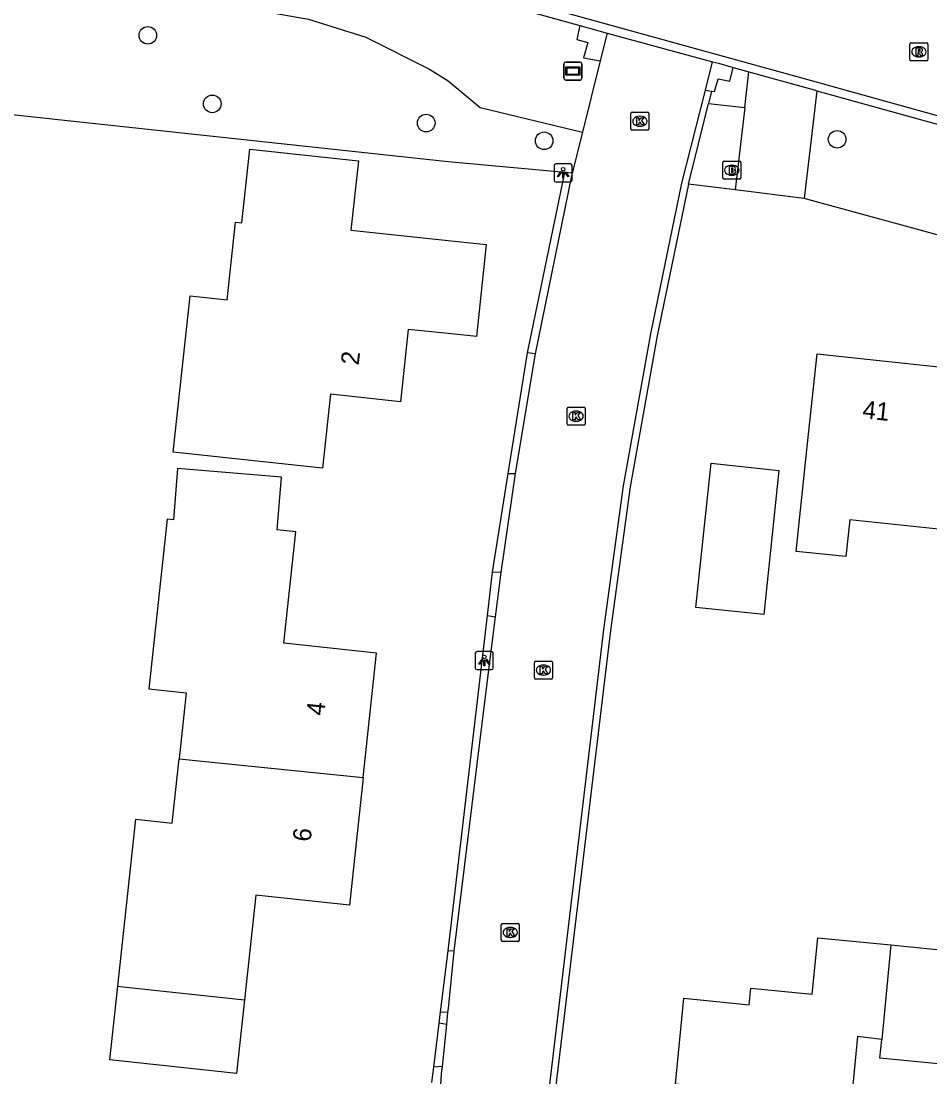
# Model space of a CAD drawing. Extents: x 162157 to 163165, y 378998 to 380775.
# Drawn here: x 162476.3 to 162526.7, y 380574.4 to 380633 of the extents above; entities that cross this region are included whole.
import ezdxf

# ---------------------------------------------------------------- set-up
doc = ezdxf.new("R2010")
doc.units = 0
for name, color, linetype in [('IMGEO_Boom', 7, 'Continuous'), ('IMGEO_Brandkraan', 7, 'Continuous'), ('IMGEO_Groenvoorziening', 7, 'Continuous'), ('IMGEO_Kolk', 7, 'Continuous'), ('IMGEO_Lichtpunt', 7, 'Continuous'), ('IMGEO_Pand', 7, 'Continuous'), ('IMGEO_Pand_nummerreeks', 7, 'Continuous'), ('IMGEO_Rijbaan_lokaal_gesloten', 7, 'Continuous'), ('IMGEO_Rijbaan_lokaal_open', 7, 'Continuous'), ('IMGEO_Rioolput', 7, 'Continuous'), ('IMGEO_Straatnaambord', 7, 'Continuous'), ('IMGEO_Voetpad_open', 7, 'Continuous')]:
    doc.layers.add(name, color=color, linetype=linetype)

msp = doc.modelspace()

# ---------------------------------------------------------------- linework, layer by layer
at = {"layer": 'IMGEO_Boom'}
for centre in [(162483.344, 380632.211), (162486.919, 380628.409), (162498.79, 380627.343), (162505.335, 380626.359), (162521.591, 380626.441)]:
    msp.add_circle(centre, 0.489, dxfattribs=at)
at = {"layer": 'IMGEO_Brandkraan'}
for p, q in [((162515.25, 380624.301), (162515.25, 380625.153)), ((162515.325, 380625.227), (162516.177, 380625.227)), ((162516.251, 380625.153), (162516.251, 380624.301)), ((162515.761, 380624.447), (162515.736, 380624.447)), ((162515.738, 380625.007), (162515.763, 380625.007)), ((162516.177, 380624.227), (162515.325, 380624.227))]:
    msp.add_line(p, q, dxfattribs=at)
for points in [[(162515.25, 380624.301), (162515.25, 380625.153)], [(162515.325, 380625.227), (162516.177, 380625.227)], [(162516.251, 380625.153), (162516.251, 380624.301)], [(162515.598, 380624.927), (162515.598, 380624.527), (162515.811, 380624.527)], [(162515.829, 380624.927), (162515.598, 380624.927)], [(162515.777, 380624.846), (162515.723, 380624.846), (162515.723, 380624.77)], [(162515.723, 380624.77), (162515.776, 380624.77)], [(162515.785, 380624.694), (162515.723, 380624.694), (162515.723, 380624.613)], [(162515.723, 380624.613), (162515.785, 380624.613)], [(162516.177, 380624.227), (162515.325, 380624.227)]]:
    msp.add_lwpolyline(points, dxfattribs=at)
for centre, radius, start, end in [((162515.327, 380625.151), 0.0765, 91.55205, 178.44795), ((162515.327, 380625.151), 0.0765, 91.55205, 178.44795), ((162516.175, 380625.151), 0.0765, 1.55205, 88.44795), ((162516.175, 380625.151), 0.0765, 1.55205, 88.44795), ((162515.778, 380624.808), 0.0379, 267.82845, 90.93552), ((162515.786, 380624.653), 0.0404, 269.87594, 90.50774), ((162515.817, 380624.778), 0.251, 268.66757, 293.53466), ((162515.833, 380624.782), 0.145, 59.4692, 91.53667), ((162515.858, 380624.829), 0.0922, 285.51372, 58.15012), ((162515.863, 380624.637), 0.105, 301.31148, 78.98903), ((162515.327, 380624.303), 0.0765, 181.55205, 268.44795), ((162515.327, 380624.303), 0.0765, 181.55205, 268.44795), ((162516.175, 380624.303), 0.0765, 271.55205, 358.44795), ((162516.175, 380624.303), 0.0765, 271.55205, 358.44795)]:
    msp.add_arc(centre, radius, start, end, dxfattribs=at)
for centre, major_axis, ratio, start_param, end_param in [((162515.737, 380624.727), (-0.387, 0.002), 0.722429, 4.712389, 7.853982), ((162515.762, 380624.727), (-0.39, 0.002), 0.717154, 1.570796, 4.712389)]:
    msp.add_ellipse(centre, major_axis=major_axis, ratio=ratio, start_param=start_param, end_param=end_param, dxfattribs=at)
at = {"layer": 'IMGEO_Groenvoorziening'}
for points in [[(162437.854, 380633.025), (162463.991, 380631.774), (162466.779, 380634.155), (162485.377, 380633.853), (162489.211, 380633.646), (162492.259, 380633.107), (162495.434, 380632.111), (162498.979, 380630.341), (162500, 380629.686), (162501.777, 380628.214), (162507.464, 380626.838)], [(162506.479, 380624.601), (162500, 380625.199), (162474.413, 380627.947), (162438.013, 380631.313)], [(162514.451, 380628.435), (162516.464, 380628.204)], [(162515.938, 380623.63), (162513.343, 380623.949)], [(162537.976, 380618.182), (162519.769, 380623.159)]]:
    msp.add_lwpolyline(points, dxfattribs=at)
at = {"layer": 'IMGEO_Kolk'}
for p, q in [((162510.149, 380627.016), (162510.149, 380627.868)), ((162510.224, 380627.942), (162511.076, 380627.942)), ((162510.637, 380627.722), (162510.662, 380627.722)), ((162511.15, 380627.868), (162511.15, 380627.016)), ((162511.076, 380626.942), (162510.224, 380626.942)), ((162510.66, 380627.162), (162510.635, 380627.162)), ((162506.679, 380611.58), (162507.531, 380611.58)), ((162506.604, 380610.654), (162506.604, 380611.506)), ((162507.092, 380611.36), (162507.117, 380611.36)), ((162507.605, 380611.506), (162507.605, 380610.654)), ((162507.531, 380610.58), (162506.679, 380610.58)), ((162507.115, 380610.8), (162507.09, 380610.8)), ((162504.867, 380597.493), (162505.719, 380597.493)), ((162504.792, 380596.567), (162504.792, 380597.419)), ((162505.28, 380597.273), (162505.305, 380597.273)), ((162505.793, 380597.419), (162505.793, 380596.567)), ((162505.719, 380596.493), (162504.867, 380596.493)), ((162505.303, 380596.713), (162505.278, 380596.713)), ((162502.956, 380582.011), (162502.956, 380582.863)), ((162503.031, 380582.937), (162503.883, 380582.937)), ((162503.957, 380582.863), (162503.957, 380582.011)), ((162503.444, 380582.717), (162503.469, 380582.717)), ((162503.883, 380581.937), (162503.031, 380581.937)), ((162503.467, 380582.157), (162503.442, 380582.157))]:
    msp.add_line(p, q, dxfattribs=at)
for points in [[(162510.149, 380627.016), (162510.149, 380627.868)], [(162510.224, 380627.942), (162511.076, 380627.942)], [(162510.47, 380627.642), (162510.593, 380627.642), (162510.593, 380627.491), (162510.723, 380627.642), (162510.887, 380627.642), (162510.741, 380627.491), (162510.894, 380627.242), (162510.742, 380627.242), (162510.657, 380627.406), (162510.593, 380627.339), (162510.593, 380627.242), (162510.47, 380627.242), (162510.47, 380627.642)], [(162511.15, 380627.868), (162511.15, 380627.016)], [(162511.076, 380626.942), (162510.224, 380626.942)], [(162506.679, 380611.58), (162507.531, 380611.58)], [(162506.604, 380610.654), (162506.604, 380611.506)], [(162506.925, 380611.28), (162507.048, 380611.28), (162507.048, 380611.129), (162507.178, 380611.28), (162507.342, 380611.28), (162507.196, 380611.129), (162507.349, 380610.88), (162507.197, 380610.88), (162507.112, 380611.044), (162507.048, 380610.977), (162507.048, 380610.88), (162506.925, 380610.88), (162506.925, 380611.28)], [(162507.605, 380611.506), (162507.605, 380610.654)], [(162507.531, 380610.58), (162506.679, 380610.58)], [(162504.867, 380597.493), (162505.719, 380597.493)], [(162504.792, 380596.567), (162504.792, 380597.419)], [(162505.113, 380597.193), (162505.236, 380597.193), (162505.236, 380597.042), (162505.366, 380597.193), (162505.53, 380597.193), (162505.384, 380597.042), (162505.537, 380596.793), (162505.385, 380596.793), (162505.3, 380596.957), (162505.236, 380596.89), (162505.236, 380596.793), (162505.113, 380596.793), (162505.113, 380597.193)], [(162505.793, 380597.419), (162505.793, 380596.567)], [(162505.719, 380596.493), (162504.867, 380596.493)], [(162502.956, 380582.011), (162502.956, 380582.863)], [(162503.031, 380582.937), (162503.883, 380582.937)], [(162503.957, 380582.863), (162503.957, 380582.011)], [(162503.277, 380582.637), (162503.4, 380582.637), (162503.4, 380582.486), (162503.53, 380582.637), (162503.694, 380582.637), (162503.548, 380582.486), (162503.701, 380582.237), (162503.549, 380582.237), (162503.464, 380582.401), (162503.4, 380582.334), (162503.4, 380582.237), (162503.277, 380582.237), (162503.277, 380582.637)], [(162503.883, 380581.937), (162503.031, 380581.937)]]:
    msp.add_lwpolyline(points, dxfattribs=at)
for centre, start, end in [((162510.226, 380627.866), 91.55205, 178.44795), ((162510.226, 380627.866), 91.55205, 178.44795), ((162511.074, 380627.866), 1.55205, 88.44795), ((162511.074, 380627.866), 1.55205, 88.44795), ((162510.226, 380627.018), 181.55205, 268.44795), ((162510.226, 380627.018), 181.55205, 268.44795), ((162511.074, 380627.018), 271.55205, 358.44795), ((162511.074, 380627.018), 271.55205, 358.44795), ((162506.681, 380611.504), 91.55205, 178.44795), ((162506.681, 380611.504), 91.55205, 178.44795), ((162507.529, 380611.504), 1.55205, 88.44795), ((162507.529, 380611.504), 1.55205, 88.44795), ((162506.681, 380610.656), 181.55205, 268.44795), ((162506.681, 380610.656), 181.55205, 268.44795), ((162507.529, 380610.656), 271.55205, 358.44795), ((162507.529, 380610.656), 271.55205, 358.44795), ((162504.869, 380597.417), 91.55205, 178.44795), ((162504.869, 380597.417), 91.55205, 178.44795), ((162505.717, 380597.417), 1.55205, 88.44795), ((162505.717, 380597.417), 1.55205, 88.44795), ((162504.869, 380596.569), 181.55205, 268.44795), ((162504.869, 380596.569), 181.55205, 268.44795), ((162505.717, 380596.569), 271.55205, 358.44795), ((162505.717, 380596.569), 271.55205, 358.44795), ((162503.033, 380582.861), 91.55205, 178.44795), ((162503.033, 380582.861), 91.55205, 178.44795), ((162503.881, 380582.861), 1.55205, 88.44795), ((162503.881, 380582.861), 1.55205, 88.44795), ((162503.033, 380582.013), 181.55205, 268.44795), ((162503.033, 380582.013), 181.55205, 268.44795), ((162503.881, 380582.013), 271.55205, 358.44795), ((162503.881, 380582.013), 271.55205, 358.44795)]:
    msp.add_arc(centre, 0.0765, start, end, dxfattribs=at)
for centre, major_axis, ratio, start_param, end_param in [((162510.636, 380627.442), (-0.387, 0.002), 0.722429, 4.712389, 7.853982), ((162510.661, 380627.442), (-0.39, 0.002), 0.717154, 1.570796, 4.712389), ((162507.091, 380611.08), (-0.387, 0.002), 0.722429, 4.712389, 7.853982), ((162507.116, 380611.08), (-0.39, 0.002), 0.717154, 1.570796, 4.712389), ((162505.279, 380596.993), (-0.387, 0.002), 0.722429, 4.712389, 7.853982), ((162505.304, 380596.993), (-0.39, 0.002), 0.717154, 1.570796, 4.712389), ((162503.443, 380582.437), (-0.387, 0.002), 0.722429, 4.712389, 7.853982), ((162503.468, 380582.437), (-0.39, 0.002), 0.717154, 1.570796, 4.712389)]:
    msp.add_ellipse(centre, major_axis=major_axis, ratio=ratio, start_param=start_param, end_param=end_param, dxfattribs=at)
at = {"layer": 'IMGEO_Lichtpunt'}
for p, q in [((162506.792, 380625.078), (162505.984, 380625.078)), ((162506.792, 380625.078), (162505.984, 380625.078)), ((162505.89, 380624.983), (162505.89, 380624.176)), ((162505.89, 380624.983), (162505.89, 380624.176)), ((162506.886, 380624.176), (162506.886, 380624.983)), ((162506.886, 380624.176), (162506.886, 380624.983)), ((162505.984, 380624.082), (162506.792, 380624.082)), ((162505.984, 380624.082), (162506.792, 380624.082)), ((162501.516, 380597.926), (162501.516, 380597.119)), ((162501.516, 380597.926), (162501.516, 380597.119)), ((162502.418, 380598.021), (162501.61, 380598.021)), ((162502.418, 380598.021), (162501.61, 380598.021)), ((162502.512, 380597.119), (162502.512, 380597.926)), ((162502.512, 380597.119), (162502.512, 380597.926)), ((162501.61, 380597.025), (162502.418, 380597.025)), ((162501.61, 380597.025), (162502.418, 380597.025))]:
    msp.add_line(p, q, dxfattribs=at)
for points in [[(162506.264, 380624.647), (162506.303, 380624.619), (162506.115, 380624.357), (162506.077, 380624.384), (162506.264, 380624.647)], [(162506.366, 380624.599), (162506.413, 380624.599), (162506.413, 380624.277), (162506.366, 380624.277), (162506.366, 380624.599)], [(162506.476, 380624.619), (162506.514, 380624.646), (162506.701, 380624.384), (162506.662, 380624.356), (162506.476, 380624.619)], [(162501.89, 380597.59), (162501.929, 380597.562), (162501.741, 380597.3), (162501.703, 380597.327), (162501.89, 380597.59)], [(162501.992, 380597.542), (162502.039, 380597.542), (162502.039, 380597.22), (162501.992, 380597.22), (162501.992, 380597.542)], [(162502.102, 380597.562), (162502.14, 380597.589), (162502.327, 380597.327), (162502.288, 380597.299), (162502.102, 380597.562)]]:
    msp.add_lwpolyline(points, dxfattribs=at)
for centre in [(162506.389, 380624.781), (162502.015, 380597.724)]:
    msp.add_circle(centre, 0.0994, dxfattribs=at)
for centre, start, end in [((162505.984, 380624.983), 90, 180), ((162505.984, 380624.983), 90, 180), ((162506.792, 380624.983), 0, 90), ((162506.792, 380624.983), 0, 90), ((162505.984, 380624.176), 180, 270), ((162505.984, 380624.176), 180, 270), ((162506.792, 380624.176), 270, 0), ((162506.792, 380624.176), 270, 360), ((162501.61, 380597.926), 90, 180), ((162501.61, 380597.926), 90, 180), ((162502.418, 380597.926), 0, 90), ((162502.418, 380597.926), 0, 90), ((162501.61, 380597.119), 180, 270), ((162501.61, 380597.119), 180, 270), ((162502.418, 380597.119), 270, 0), ((162502.418, 380597.119), 270, 360)]:
    msp.add_arc(centre, 0.0946, start, end, dxfattribs=at)
at = {"layer": 'IMGEO_Pand'}
for points in [[(162485.685, 380617.752), (162487.743, 380617.531), (162488.208, 380621.852), (162488.56, 380621.814), (162489, 380625.896), (162495.03, 380625.247), (162494.616, 380621.403), (162500, 380620.836), (162502.118, 380620.613), (162501.586, 380615.506), (162500, 380615.669), (162497.794, 380615.896), (162497.362, 380611.883), (162493.475, 380612.302), (162493.033, 380608.196), (162484.752, 380609.088), (162485.685, 380617.752)], [(162527.914, 380604.729), (162522.289, 380605.325), (162522.073, 380603.287), (162519.315, 380603.579), (162519.949, 380609.559), (162520.476, 380614.531), (162527.565, 380613.78)], [(162495.295, 380591.027), (162496.039, 380597.94), (162490.887, 380598.495), (162491.55, 380604.656), (162490.528, 380604.766), (162490.766, 380607.701), (162484.995, 380608.169), (162484.765, 380605.338), (162484.419, 380605.366), (162483.408, 380595.952), (162485.476, 380595.729), (162485.082, 380592.069)], [(162517.515, 380600.073), (162513.752, 380600.472), (162514.6, 380608.468), (162518.363, 380608.069), (162517.515, 380600.073)], [(162481.674, 380579.453), (162482.671, 380588.712), (162484.697, 380588.494), (162485.082, 380592.069)], [(162485.082, 380592.069), (162495.295, 380591.027)], [(162495.295, 380591.027), (162494.532, 380583.945), (162489.336, 380584.504), (162488.71, 380578.696)], [(162524.068, 380576.504), (162522.729, 380576.659), (162521.978, 380568.973), (162513.98, 380569.754), (162514.38, 380573.843), (162512.616, 380574.015), (162513.081, 380578.78), (162516.714, 380578.426), (162516.804, 380579.351), (162520.208, 380579.02), (162520.512, 380582.14), (162524.58, 380581.742)], [(162524.58, 380581.742), (162524.068, 380576.504)], [(162524.58, 380581.742), (162528.213, 380581.387)], [(162488.71, 380578.696), (162488.27, 380574.611), (162481.234, 380575.368), (162481.674, 380579.453)], [(162481.674, 380579.453), (162482.144, 380579.402), (162488.71, 380578.696)], [(162527.593, 380575.103), (162523.966, 380575.457), (162524.068, 380576.504)]]:
    msp.add_lwpolyline(points, dxfattribs=at)
at = {"layer": 'IMGEO_Rijbaan_lokaal_gesloten'}
for points in [[(162477.228, 380639.674), (162480.976, 380639.284), (162491.138, 380637.273), (162500, 380634.796), (162507.306, 380632.754)], [(162600.248, 380607.426), (162547.05, 380622.206), (162522.044, 380629.176), (162520.438, 380629.619), (162500, 380635.264), (162493.395, 380637.088)], [(162507.306, 380632.754), (162508.833, 380632.327)], [(162508.833, 380632.327), (162514.682, 380630.745)], [(162514.682, 380630.745), (162515.001, 380630.659), (162515.816, 380630.433)], [(162515.816, 380630.433), (162516.692, 380630.19)], [(162516.692, 380630.19), (162520.317, 380629.183), (162520.472, 380629.14)], [(162520.472, 380629.14), (162539.243, 380623.93)]]:
    msp.add_lwpolyline(points, dxfattribs=at)
at = {"layer": 'IMGEO_Rijbaan_lokaal_open'}
for points in [[(162507.306, 380632.754), (162507.151, 380631.978), (162507.766, 380631.808), (162507.522, 380630.962), (162508.449, 380630.789)], [(162508.833, 380632.327), (162508.449, 380630.789)], [(162508.449, 380630.789), (162507.464, 380626.838)], [(162514.282, 380629.177), (162514.682, 380630.745)], [(162514.62, 380629.116), (162514.784, 380629.087), (162514.99, 380629.805), (162515.633, 380629.66), (162515.816, 380630.433)], [(162505.493, 380572.753), (162508.646, 380599.247), (162509.739, 380607.207), (162511.252, 380615.648), (162512.967, 380624.014), (162514.282, 380629.177)], [(162514.282, 380629.177), (162514.62, 380629.116)], [(162514.62, 380629.116), (162514.451, 380628.435)], [(162513.343, 380623.949), (162514.451, 380628.435)], [(162507.464, 380626.838), (162506.896, 380624.563)], [(162504.412, 380614.587), (162506.479, 380624.601)], [(162506.896, 380624.563), (162506.861, 380624.423), (162504.841, 380614.547)], [(162506.896, 380624.563), (162506.479, 380624.601)], [(162513.343, 380623.949), (162511.606, 380615.531), (162510.109, 380607.162), (162509.012, 380599.183), (162505.8, 380572.406)], [(162504.841, 380614.547), (162503.735, 380607.908)], [(162504.841, 380614.547), (162504.412, 380614.587)], [(162502.472, 380602.43), (162503.344, 380607.897)], [(162503.735, 380607.908), (162502.934, 380602.411)], [(162503.344, 380607.897), (162503.735, 380607.908)], [(162502.934, 380602.411), (162502.472, 380602.43)], [(162502.934, 380602.411), (162502.624, 380599.941)], [(162500, 380581.422), (162502.189, 380600.029)], [(162502.624, 380599.941), (162502.032, 380595.226), (162500.328, 380581.389)], [(162502.189, 380600.029), (162502.624, 380599.941)], [(162500.328, 380581.389), (162500, 380578.214), (162499.979, 380578.011)], [(162500.328, 380581.389), (162500, 380581.422)], [(162499.508, 380577.409), (162499.584, 380578.026)], [(162499.584, 380578.026), (162499.979, 380578.011)], [(162499.979, 380578.011), (162499.909, 380577.331)], [(162499.909, 380577.331), (162499.508, 380577.409)], [(162499.909, 380577.331), (162499.667, 380574.99)], [(162499.104, 380574.108), (162499.208, 380574.957)], [(162499.667, 380574.99), (162499.208, 380574.957)]]:
    msp.add_lwpolyline(points, dxfattribs=at)
msp.add_arc((162517.948, 380572.877), 18.402, 173.4078, 192.76282, dxfattribs=at)
at = {"layer": 'IMGEO_Rioolput'}
for p, q in [((162525.629, 380630.87), (162525.629, 380631.722)), ((162525.704, 380631.796), (162526.556, 380631.796)), ((162526.117, 380631.576), (162526.142, 380631.576)), ((162526.63, 380631.722), (162526.63, 380630.87)), ((162526.14, 380631.016), (162526.115, 380631.016)), ((162526.556, 380630.796), (162525.704, 380630.796))]:
    msp.add_line(p, q, dxfattribs=at)
for points in [[(162525.629, 380630.87), (162525.629, 380631.722)], [(162525.704, 380631.796), (162526.556, 380631.796)], [(162526.218, 380631.494), (162525.966, 380631.496), (162525.966, 380631.096)], [(162526.63, 380631.722), (162526.63, 380630.87)], [(162525.966, 380631.096), (162526.09, 380631.096), (162526.09, 380631.258), (162526.101, 380631.258)], [(162526.144, 380631.415), (162526.09, 380631.415), (162526.09, 380631.334)], [(162526.09, 380631.334), (162526.142, 380631.334)], [(162526.148, 380631.229), (162526.219, 380631.096), (162526.359, 380631.096), (162526.294, 380631.222)], [(162526.556, 380630.796), (162525.704, 380630.796)]]:
    msp.add_lwpolyline(points, dxfattribs=at)
for centre, radius, start, end in [((162525.706, 380631.72), 0.0765, 91.55205, 178.44795), ((162525.706, 380631.72), 0.0765, 91.55205, 178.44795), ((162526.217, 380631.384), 0.109, 350.36119, 89.41601), ((162526.554, 380631.72), 0.0765, 1.55205, 88.44795), ((162526.554, 380631.72), 0.0765, 1.55205, 88.44795), ((162526.1, 380631.205), 0.0533, 26.02933, 88.69889), ((162526.126, 380631.523), 0.19, 274.7715, 282.96867), ((162526.15, 380631.319), 0.0964, 77.00612, 93.18647), ((162526.164, 380631.376), 0.0378, 276.66336, 79.67722), ((162526.215, 380631.384), 0.112, 277.58423, 350.98172), ((162526.199, 380631.169), 0.108, 29.51342, 73.79051), ((162525.706, 380630.872), 0.0765, 181.55205, 268.44795), ((162525.706, 380630.872), 0.0765, 181.55205, 268.44795), ((162526.554, 380630.872), 0.0765, 271.55205, 358.44795), ((162526.554, 380630.872), 0.0765, 271.55205, 358.44795)]:
    msp.add_arc(centre, radius, start, end, dxfattribs=at)
for centre, major_axis, ratio, start_param, end_param in [((162526.116, 380631.296), (-0.387, 0.002), 0.722429, 4.712389, 7.853982), ((162526.141, 380631.296), (-0.39, 0.002), 0.717154, 1.570796, 4.712389)]:
    msp.add_ellipse(centre, major_axis=major_axis, ratio=ratio, start_param=start_param, end_param=end_param, dxfattribs=at)
at = {"layer": 'IMGEO_Straatnaambord'}
for p, q in [((162506.434, 380629.828), (162506.434, 380630.628)), ((162506.434, 380630.628), (162506.434, 380629.828)), ((162506.534, 380630.728), (162507.324, 380630.728)), ((162507.324, 380630.728), (162506.534, 380630.728)), ((162507.424, 380630.628), (162507.424, 380629.828)), ((162507.424, 380629.828), (162507.424, 380630.628)), ((162507.324, 380629.728), (162506.534, 380629.728)), ((162506.534, 380629.728), (162507.324, 380629.728))]:
    msp.add_line(p, q, dxfattribs=at)
for points in [[(162506.535, 380630.46), (162507.323, 380630.46), (162507.323, 380629.996), (162506.535, 380629.996), (162506.535, 380630.46)], [(162506.6, 380630.395), (162506.6, 380630.061), (162507.258, 380630.061), (162507.258, 380630.395), (162506.6, 380630.395)]]:
    msp.add_lwpolyline(points, dxfattribs=at)
for centre, start, end in [((162506.534, 380630.628), 90, 180), ((162506.534, 380630.628), 90, 180), ((162507.324, 380630.628), 0, 90), ((162507.324, 380630.628), 360, 90), ((162506.534, 380629.828), 180, 270), ((162506.534, 380629.828), 180, 270), ((162507.324, 380629.828), 270, 0), ((162507.324, 380629.828), 270, 0)]:
    msp.add_arc(centre, 0.1, start, end, dxfattribs=at)
at = {"layer": 'IMGEO_Voetpad_open'}
for points in [[(162516.464, 380628.204), (162516.692, 380630.19)], [(162520.472, 380629.14), (162520.266, 380627.386), (162519.769, 380623.159)], [(162516.464, 380628.204), (162515.938, 380623.63)], [(162519.769, 380623.159), (162515.938, 380623.63)], [(162503.344, 380607.897), (162504.412, 380614.587)], [(162502.189, 380600.029), (162502.472, 380602.43)], [(162499.584, 380578.026), (162500, 380581.422)], [(162499.208, 380574.957), (162499.508, 380577.409)]]:
    msp.add_lwpolyline(points, dxfattribs=at)

# ---------------------------------------------------------------- texts
at = {"layer": 'IMGEO_Pand_nummerreeks'}
for s, rotation, p in [('2', 83.85576, (162495.043, 380613.883)), ('41', 353.95271, (162522.966, 380610.969)), ('4', 83.85237, (162493.127, 380594.437)), ('6', 83.854, (162492.373, 380587.439))]:
    msp.add_text(s, height=1, rotation=rotation, dxfattribs=at).set_placement(p)

doc.saveas('drawing.dxf')
